Omron CX-Programmer project NuevoProyecto (CX-Programmer 9.50)

# PLC NuevoPLC1: CP1L-E EM

## Program P1_5 (cyclic task 0)
Local symbols
B 100.00 BOOL
p 0.00 BOOL

### Section Sección1_Programa_principal

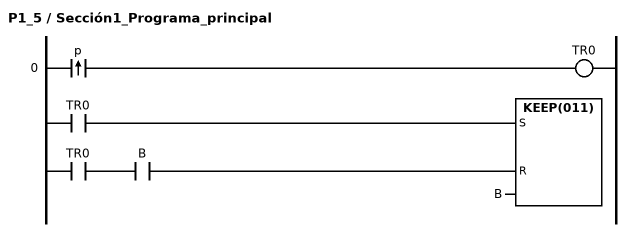
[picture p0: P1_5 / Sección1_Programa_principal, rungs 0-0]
; rung 0
@LD p
OUT TR0
LD TR0
AND B
KEEP(011) B

### Section END
; rung 0
END(001)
